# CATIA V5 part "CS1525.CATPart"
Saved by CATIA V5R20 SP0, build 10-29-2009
Part number: CS1525
Revision: 4
Definition: design
Nomenclature: CS1525
Source: made
Description: NOT SPECIFIED
Bounding box of the stored display mesh (mm): x -23.825 to 24, y -24 to 24, z -45 to 12
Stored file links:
  C:\Users\Raffaele\Desktop\3D X SITO CF\BOLEX\20-TILTED COLUMN SUPPORT\CS1525.CATPart
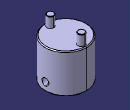
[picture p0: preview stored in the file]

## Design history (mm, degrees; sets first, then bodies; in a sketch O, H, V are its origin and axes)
Body1 "MANIFOLD_SOLID_BREP #711" (main body)
  Solid1: solid without history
